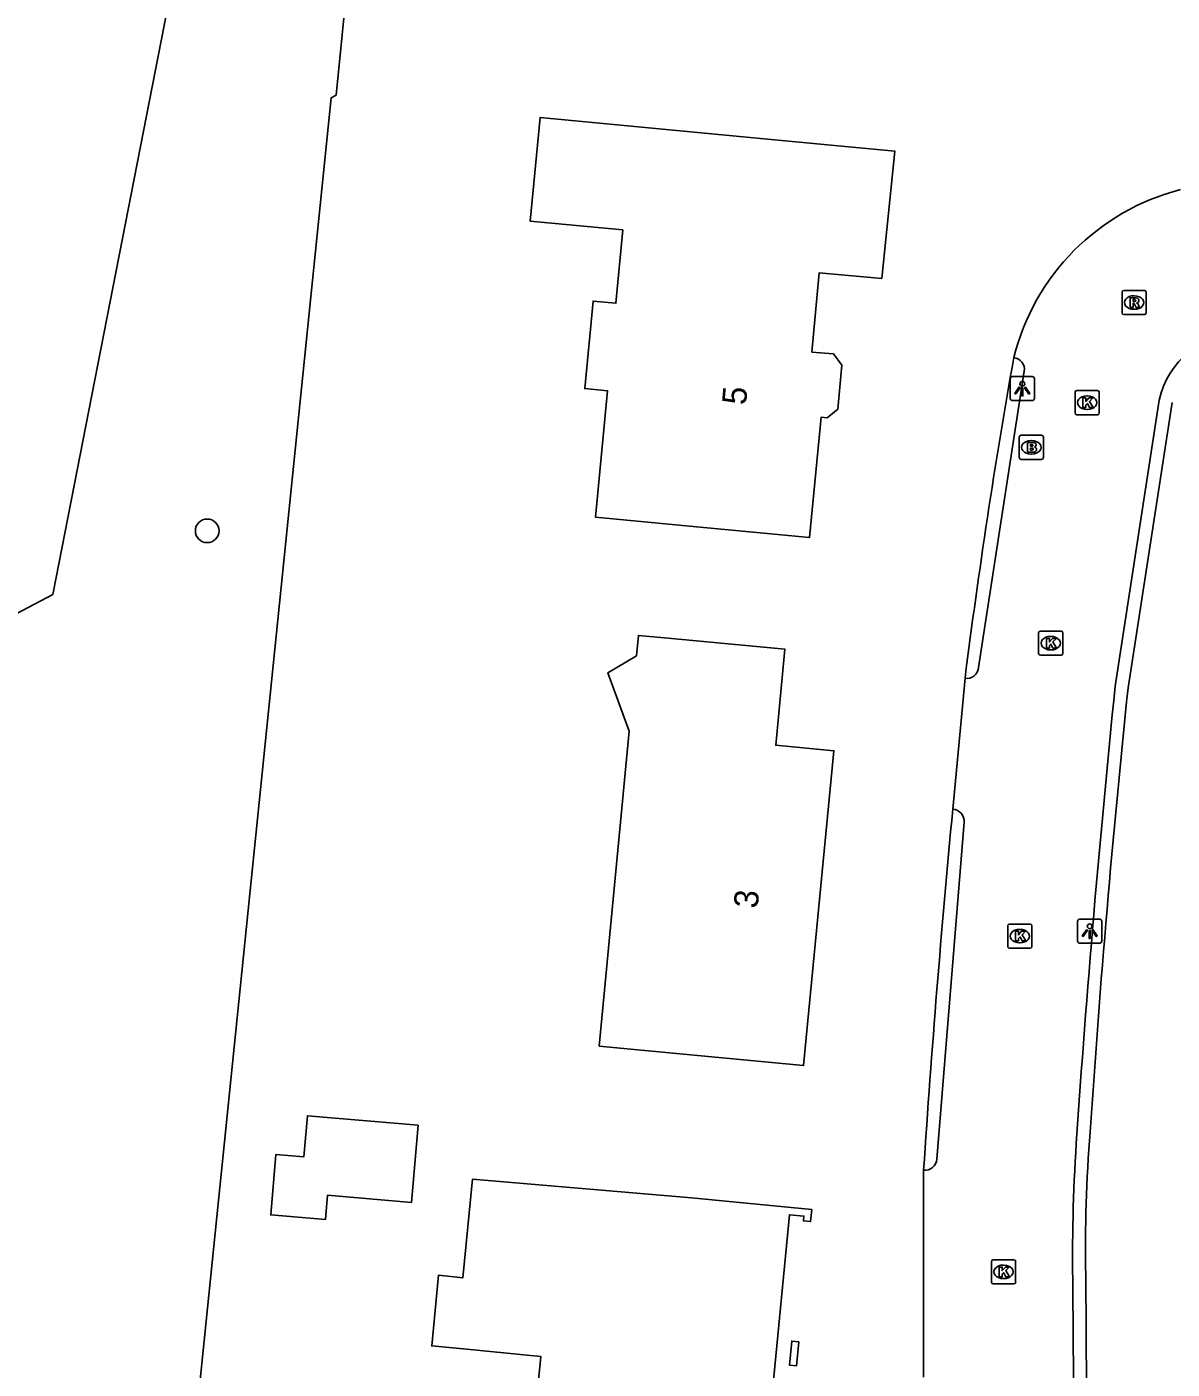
# Model space of a CAD drawing. Extents: x 162157 to 163165, y 378998 to 380775.
# Drawn here: x 162289.4 to 162336.8, y 380647 to 380702.5 of the extents above; entities that cross this region are included whole.
import ezdxf

# ---------------------------------------------------------------- set-up
doc = ezdxf.new("R2010")
doc.units = 0
for name, color, linetype in [('IMGEO_Boom', 7, 'Continuous'), ('IMGEO_Brandkraan', 7, 'Continuous'), ('IMGEO_Groenvoorziening', 7, 'Continuous'), ('IMGEO_Kolk', 7, 'Continuous'), ('IMGEO_Lichtpunt', 7, 'Continuous'), ('IMGEO_Pand', 7, 'Continuous'), ('IMGEO_Pand_nummerreeks', 7, 'Continuous'), ('IMGEO_Rijbaan_lokaal_open', 7, 'Continuous'), ('IMGEO_Rioolput', 7, 'Continuous'), ('IMGEO_Voetpad_open', 7, 'Continuous')]:
    doc.layers.add(name, color=color, linetype=linetype)

msp = doc.modelspace()

# ---------------------------------------------------------------- linework, layer by layer
at = {"layer": 'IMGEO_Boom'}
msp.add_circle((162296.826, 380681.67), 0.489, dxfattribs=at)
at = {"layer": 'IMGEO_Brandkraan'}
for p, q in [((162330.438, 380684.702), (162330.438, 380685.554)), ((162330.513, 380685.628), (162331.365, 380685.628)), ((162330.926, 380685.408), (162330.951, 380685.408)), ((162331.439, 380685.554), (162331.439, 380684.702)), ((162330.949, 380684.848), (162330.924, 380684.848)), ((162331.365, 380684.628), (162330.513, 380684.628))]:
    msp.add_line(p, q, dxfattribs=at)
for points in [[(162330.438, 380684.702), (162330.438, 380685.554)], [(162330.513, 380685.628), (162331.365, 380685.628)], [(162330.786, 380685.328), (162330.786, 380684.928), (162330.999, 380684.928)], [(162331.017, 380685.328), (162330.786, 380685.328)], [(162330.965, 380685.247), (162330.911, 380685.247), (162330.911, 380685.171)], [(162331.439, 380685.554), (162331.439, 380684.702)], [(162330.911, 380685.171), (162330.964, 380685.171)], [(162330.973, 380685.095), (162330.911, 380685.095), (162330.911, 380685.014)], [(162330.911, 380685.014), (162330.973, 380685.014)], [(162331.365, 380684.628), (162330.513, 380684.628)]]:
    msp.add_lwpolyline(points, dxfattribs=at)
for centre, radius, start, end in [((162330.515, 380685.552), 0.0765, 91.552, 178.448), ((162330.515, 380685.552), 0.0765, 91.552, 178.448), ((162330.966, 380685.209), 0.0379, 267.8285, 90.9355), ((162331.021, 380685.183), 0.145, 59.4692, 91.5367), ((162331.046, 380685.23), 0.0922, 285.5137, 58.1501), ((162331.363, 380685.552), 0.0765, 1.552, 88.448), ((162331.363, 380685.552), 0.0765, 1.552, 88.448), ((162330.515, 380684.704), 0.0765, 181.552, 268.448), ((162330.515, 380684.704), 0.0765, 181.552, 268.448), ((162330.974, 380685.054), 0.0404, 269.8759, 90.5077), ((162331.005, 380685.179), 0.251, 268.6676, 293.5347), ((162331.051, 380685.038), 0.105, 301.3115, 78.989), ((162331.363, 380684.704), 0.0765, 271.552, 358.448), ((162331.363, 380684.704), 0.0765, 271.552, 358.448)]:
    msp.add_arc(centre, radius, start, end, dxfattribs=at)
for centre, major_axis, ratio, start_param, end_param in [((162330.925, 380685.128), (-0.387, 0.002), 0.722429, 4.712389, 7.853982), ((162330.95, 380685.128), (-0.39, 0.002), 0.717154, 1.570796, 4.712389)]:
    msp.add_ellipse(centre, major_axis=major_axis, ratio=ratio, start_param=start_param, end_param=end_param, dxfattribs=at)
at = {"layer": 'IMGEO_Groenvoorziening'}
for points in [[(162295.473, 380636.096), (162301.962, 380699.607), (162302.171, 380699.713), (162304.371, 380721.939), (162315.245, 380730.525)], [(162288.388, 380677.953), (162290.44, 380679.036), (162295.923, 380707.125), (162296.214, 380708.615), (162296.259, 380708.847)]]:
    msp.add_lwpolyline(points, dxfattribs=at)
at = {"layer": 'IMGEO_Kolk'}
for p, q in [((162332.825, 380687.48), (162333.677, 380687.48)), ((162332.75, 380686.554), (162332.75, 380687.406)), ((162333.238, 380687.26), (162333.263, 380687.26)), ((162333.751, 380687.406), (162333.751, 380686.554)), ((162333.677, 380686.48), (162332.825, 380686.48)), ((162333.261, 380686.7), (162333.236, 380686.7)), ((162331.316, 380677.517), (162332.168, 380677.517)), ((162331.241, 380676.591), (162331.241, 380677.443)), ((162331.729, 380677.297), (162331.754, 380677.297)), ((162332.242, 380677.443), (162332.242, 380676.591)), ((162332.168, 380676.517), (162331.316, 380676.517)), ((162331.752, 380676.737), (162331.727, 380676.737)), ((162329.963, 380664.459), (162329.963, 380665.311)), ((162330.038, 380665.385), (162330.89, 380665.385)), ((162330.964, 380665.311), (162330.964, 380664.459)), ((162330.451, 380665.165), (162330.476, 380665.165)), ((162330.89, 380664.385), (162330.038, 380664.385)), ((162330.474, 380664.605), (162330.449, 380664.605)), ((162329.29, 380650.556), (162329.29, 380651.408)), ((162329.365, 380651.482), (162330.217, 380651.482)), ((162330.291, 380651.408), (162330.291, 380650.556)), ((162329.778, 380651.262), (162329.803, 380651.262)), ((162330.217, 380650.482), (162329.365, 380650.482)), ((162329.801, 380650.702), (162329.776, 380650.702))]:
    msp.add_line(p, q, dxfattribs=at)
for points in [[(162332.825, 380687.48), (162333.677, 380687.48)], [(162332.75, 380686.554), (162332.75, 380687.406)], [(162333.071, 380687.18), (162333.194, 380687.18), (162333.194, 380687.029), (162333.324, 380687.18), (162333.488, 380687.18), (162333.342, 380687.029), (162333.495, 380686.78), (162333.343, 380686.78), (162333.258, 380686.944), (162333.194, 380686.877), (162333.194, 380686.78), (162333.071, 380686.78), (162333.071, 380687.18)], [(162333.751, 380687.406), (162333.751, 380686.554)], [(162333.677, 380686.48), (162332.825, 380686.48)], [(162331.316, 380677.517), (162332.168, 380677.517)], [(162331.241, 380676.591), (162331.241, 380677.443)], [(162331.562, 380677.217), (162331.685, 380677.217), (162331.685, 380677.066), (162331.815, 380677.217), (162331.979, 380677.217), (162331.833, 380677.066), (162331.986, 380676.817), (162331.834, 380676.817), (162331.749, 380676.981), (162331.685, 380676.914), (162331.685, 380676.817), (162331.562, 380676.817), (162331.562, 380677.217)], [(162332.242, 380677.443), (162332.242, 380676.591)], [(162332.168, 380676.517), (162331.316, 380676.517)], [(162329.963, 380664.459), (162329.963, 380665.311)], [(162330.038, 380665.385), (162330.89, 380665.385)], [(162330.964, 380665.311), (162330.964, 380664.459)], [(162330.284, 380665.085), (162330.407, 380665.085), (162330.407, 380664.934), (162330.537, 380665.085), (162330.701, 380665.085), (162330.555, 380664.934), (162330.708, 380664.685), (162330.556, 380664.685), (162330.471, 380664.849), (162330.407, 380664.782), (162330.407, 380664.685), (162330.284, 380664.685), (162330.284, 380665.085)], [(162330.89, 380664.385), (162330.038, 380664.385)], [(162329.29, 380650.556), (162329.29, 380651.408)], [(162329.365, 380651.482), (162330.217, 380651.482)], [(162330.291, 380651.408), (162330.291, 380650.556)], [(162329.611, 380651.182), (162329.734, 380651.182), (162329.734, 380651.031), (162329.864, 380651.182), (162330.028, 380651.182), (162329.882, 380651.031), (162330.035, 380650.782), (162329.883, 380650.782), (162329.798, 380650.946), (162329.734, 380650.879), (162329.734, 380650.782), (162329.611, 380650.782), (162329.611, 380651.182)], [(162330.217, 380650.482), (162329.365, 380650.482)]]:
    msp.add_lwpolyline(points, dxfattribs=at)
for centre, start, end in [((162332.827, 380687.404), 91.552, 178.448), ((162332.827, 380687.404), 91.552, 178.448), ((162333.675, 380687.404), 1.552, 88.448), ((162333.675, 380687.404), 1.552, 88.448), ((162332.827, 380686.556), 181.552, 268.448), ((162332.827, 380686.556), 181.552, 268.448), ((162333.675, 380686.556), 271.552, 358.448), ((162333.675, 380686.556), 271.552, 358.448), ((162331.318, 380677.441), 91.552, 178.448), ((162331.318, 380677.441), 91.552, 178.448), ((162332.166, 380677.441), 1.552, 88.448), ((162332.166, 380677.441), 1.552, 88.448), ((162331.318, 380676.593), 181.552, 268.448), ((162331.318, 380676.593), 181.552, 268.448), ((162332.166, 380676.593), 271.552, 358.448), ((162332.166, 380676.593), 271.552, 358.448), ((162330.04, 380665.309), 91.552, 178.448), ((162330.04, 380665.309), 91.552, 178.448), ((162330.888, 380665.309), 1.552, 88.448), ((162330.888, 380665.309), 1.552, 88.448), ((162330.04, 380664.461), 181.552, 268.448), ((162330.04, 380664.461), 181.552, 268.448), ((162330.888, 380664.461), 271.552, 358.448), ((162330.888, 380664.461), 271.552, 358.448), ((162329.367, 380651.406), 91.552, 178.448), ((162329.367, 380651.406), 91.552, 178.448), ((162330.215, 380651.406), 1.552, 88.448), ((162330.215, 380651.406), 1.552, 88.448), ((162329.367, 380650.558), 181.552, 268.448), ((162329.367, 380650.558), 181.552, 268.448), ((162330.215, 380650.558), 271.552, 358.448), ((162330.215, 380650.558), 271.552, 358.448)]:
    msp.add_arc(centre, 0.0765, start, end, dxfattribs=at)
for centre, major_axis, ratio, start_param, end_param in [((162333.237, 380686.98), (-0.387, 0.002), 0.722429, 4.712389, 7.853982), ((162333.262, 380686.98), (-0.39, 0.002), 0.717154, 1.570796, 4.712389), ((162331.728, 380677.017), (-0.387, 0.002), 0.722429, 4.712389, 7.853982), ((162331.753, 380677.017), (-0.39, 0.002), 0.717154, 1.570796, 4.712389), ((162330.45, 380664.885), (-0.387, 0.002), 0.722429, 4.712389, 7.853982), ((162330.475, 380664.885), (-0.39, 0.002), 0.717154, 1.570796, 4.712389), ((162329.777, 380650.982), (-0.387, 0.002), 0.722429, 4.712389, 7.853982), ((162329.802, 380650.982), (-0.39, 0.002), 0.717154, 1.570796, 4.712389)]:
    msp.add_ellipse(centre, major_axis=major_axis, ratio=ratio, start_param=start_param, end_param=end_param, dxfattribs=at)
at = {"layer": 'IMGEO_Lichtpunt'}
for p, q in [((162330.97, 380688.057), (162330.162, 380688.057)), ((162330.97, 380688.057), (162330.162, 380688.057)), ((162330.068, 380687.962), (162330.068, 380687.155)), ((162330.068, 380687.962), (162330.068, 380687.155)), ((162331.064, 380687.155), (162331.064, 380687.962)), ((162331.064, 380687.155), (162331.064, 380687.962)), ((162330.162, 380687.061), (162330.97, 380687.061)), ((162330.162, 380687.061), (162330.97, 380687.061)), ((162332.857, 380665.494), (162332.857, 380664.687)), ((162332.857, 380665.494), (162332.857, 380664.687)), ((162333.759, 380665.589), (162332.951, 380665.589)), ((162333.759, 380665.589), (162332.951, 380665.589)), ((162333.853, 380664.687), (162333.853, 380665.494)), ((162333.853, 380664.687), (162333.853, 380665.494)), ((162332.951, 380664.593), (162333.759, 380664.593)), ((162332.951, 380664.593), (162333.759, 380664.593))]:
    msp.add_line(p, q, dxfattribs=at)
for points in [[(162330.442, 380687.626), (162330.481, 380687.598), (162330.293, 380687.336), (162330.255, 380687.363), (162330.442, 380687.626)], [(162330.544, 380687.578), (162330.591, 380687.578), (162330.591, 380687.256), (162330.544, 380687.256), (162330.544, 380687.578)], [(162330.654, 380687.598), (162330.692, 380687.625), (162330.879, 380687.363), (162330.84, 380687.335), (162330.654, 380687.598)], [(162333.231, 380665.158), (162333.27, 380665.13), (162333.082, 380664.868), (162333.044, 380664.895), (162333.231, 380665.158)], [(162333.333, 380665.11), (162333.38, 380665.11), (162333.38, 380664.788), (162333.333, 380664.788), (162333.333, 380665.11)], [(162333.443, 380665.13), (162333.481, 380665.157), (162333.668, 380664.895), (162333.629, 380664.867), (162333.443, 380665.13)]]:
    msp.add_lwpolyline(points, dxfattribs=at)
for centre in [(162330.567, 380687.76), (162333.356, 380665.292)]:
    msp.add_circle(centre, 0.0994, dxfattribs=at)
for centre, start, end in [((162330.162, 380687.962), 90, 180), ((162330.162, 380687.962), 90, 180), ((162330.97, 380687.962), 0, 90), ((162330.97, 380687.962), 0, 90), ((162330.162, 380687.155), 180, 270), ((162330.162, 380687.155), 180, 270), ((162330.97, 380687.155), 270, 0), ((162330.97, 380687.155), 270, 360), ((162332.951, 380665.494), 90, 180), ((162332.951, 380665.494), 90, 180), ((162333.759, 380665.494), 0, 90), ((162333.759, 380665.494), 0, 90), ((162332.951, 380664.687), 180, 270), ((162332.951, 380664.687), 180, 270), ((162333.759, 380664.687), 270, 0), ((162333.759, 380664.687), 270, 360)]:
    msp.add_arc(centre, 0.0946, start, end, dxfattribs=at)
at = {"layer": 'IMGEO_Pand'}
for points in [[(162320.315, 380697.862), (162310.604, 380698.787), (162310.195, 380694.496), (162314.029, 380694.132), (162313.741, 380691.095), (162312.796, 380691.186), (162312.452, 380687.562), (162313.398, 380687.472), (162312.9, 380682.235), (162316.786, 380681.865), (162321.763, 380681.391), (162322.238, 380686.371), (162322.487, 380686.348), (162322.926, 380686.702), (162323.1, 380688.529), (162322.745, 380688.994), (162321.859, 380689.074), (162322.158, 380692.357), (162324.745, 380692.12), (162325.292, 380697.388), (162320.315, 380697.862)], [(162316.538, 380660), (162321.515, 380659.526), (162322.768, 380672.561), (162320.363, 380672.789), (162320.739, 380676.765), (162315.762, 380677.238), (162314.675, 380677.341), (162314.594, 380676.488), (162313.406, 380675.788), (162314.298, 380673.373), (162313.056, 380660.331), (162316.538, 380660)], [(162305.556, 380657.055), (162300.973, 380657.449), (162300.827, 380655.745), (162299.672, 380655.844), (162299.457, 380653.34), (162301.721, 380653.146), (162301.808, 380654.155), (162305.281, 380653.857), (162305.556, 380657.055)], [(162320.068, 380644.491), (162320.926, 380653.349), (162321.523, 380653.291), (162321.504, 380653.092), (162321.803, 380653.063), (162321.851, 380653.561), (162316.875, 380654.044), (162307.809, 380654.824), (162307.413, 380650.734), (162306.396, 380650.843), (162306.122, 380647.916), (162307.848, 380647.749), (162309.937, 380647.547), (162310.634, 380647.479), (162310.118, 380642.154)], [(162321.32, 380648.087), (162321.022, 380648.116), (162320.925, 380647.12), (162321.224, 380647.091), (162321.32, 380648.087)]]:
    msp.add_lwpolyline(points, dxfattribs=at)
at = {"layer": 'IMGEO_Rijbaan_lokaal_open'}
for points in [[(162328.758, 380676.005), (162330.646, 380688.277)], [(162336.232, 380687.084), (162334.412, 380675.231)], [(162328.196, 380675.567), (162327.687, 380670.14)], [(162327.03, 380655.644), (162328.159, 380669.604)], [(162326.48, 380655.187), (162326.471, 380646.623)], [(162332.659, 380650.286), (162332.751, 380637.296)]]:
    msp.add_lwpolyline(points, dxfattribs=at)
for centre, radius, start, end in [((162339.49, 380686.545), 9.554, 104.4037, 166.0844), ((162339.66, 380686.326), 3.511, 90.0324, 167.5356), ((162330.157, 380688.352), 0.495, 351.2954, 83.1537), ((162328.282, 380676.037), 0.477, 259.6614, 356.2014), ((162880.043, 380619.242), 548.496, 174.14115, 176.12624), ((162327.659, 380669.64), 0.501, 355.9386, 86.7955), ((162403.824, 380651.624), 71.177, 176.23553, 181.07699), ((162326.534, 380655.681), 0.497, 263.7704, 355.6766)]:
    msp.add_arc(centre, radius, start, end, dxfattribs=at)
at = {"layer": 'IMGEO_Rioolput'}
for p, q in [((162334.693, 380690.698), (162334.693, 380691.55)), ((162334.768, 380691.624), (162335.62, 380691.624)), ((162335.181, 380691.404), (162335.206, 380691.404)), ((162335.694, 380691.55), (162335.694, 380690.698)), ((162335.204, 380690.844), (162335.179, 380690.844)), ((162335.62, 380690.624), (162334.768, 380690.624))]:
    msp.add_line(p, q, dxfattribs=at)
for points in [[(162334.693, 380690.698), (162334.693, 380691.55)], [(162334.768, 380691.624), (162335.62, 380691.624)], [(162335.694, 380691.55), (162335.694, 380690.698)], [(162335.282, 380691.322), (162335.03, 380691.324), (162335.03, 380690.924)], [(162335.03, 380690.924), (162335.154, 380690.924), (162335.154, 380691.086), (162335.165, 380691.086)], [(162335.208, 380691.243), (162335.154, 380691.243), (162335.154, 380691.162)], [(162335.154, 380691.162), (162335.206, 380691.162)], [(162335.212, 380691.057), (162335.283, 380690.924), (162335.423, 380690.924), (162335.358, 380691.05)], [(162335.62, 380690.624), (162334.768, 380690.624)]]:
    msp.add_lwpolyline(points, dxfattribs=at)
for centre, radius, start, end in [((162334.77, 380691.548), 0.0765, 91.552, 178.448), ((162334.77, 380691.548), 0.0765, 91.552, 178.448), ((162335.618, 380691.548), 0.0765, 1.552, 88.448), ((162335.618, 380691.548), 0.0765, 1.552, 88.448), ((162335.164, 380691.033), 0.0533, 26.0293, 88.6989), ((162335.19, 380691.351), 0.19, 274.7715, 282.9687), ((162335.214, 380691.147), 0.0964, 77.0061, 93.1865), ((162335.228, 380691.204), 0.0378, 276.6634, 79.6772), ((162335.281, 380691.212), 0.109, 350.3612, 89.416), ((162335.279, 380691.212), 0.112, 277.5842, 350.9817), ((162335.263, 380690.997), 0.108, 29.5134, 73.7905), ((162334.77, 380690.7), 0.0765, 181.552, 268.448), ((162334.77, 380690.7), 0.0765, 181.552, 268.448), ((162335.618, 380690.7), 0.0765, 271.552, 358.448), ((162335.618, 380690.7), 0.0765, 271.552, 358.448)]:
    msp.add_arc(centre, radius, start, end, dxfattribs=at)
for centre, major_axis, ratio, start_param, end_param in [((162335.18, 380691.124), (-0.387, 0.002), 0.722429, 4.712389, 7.853982), ((162335.205, 380691.124), (-0.39, 0.002), 0.717154, 1.570796, 4.712389)]:
    msp.add_ellipse(centre, major_axis=major_axis, ratio=ratio, start_param=start_param, end_param=end_param, dxfattribs=at)
at = {"layer": 'IMGEO_Voetpad_open'}
for points in [[(162336.768, 380686.979), (162334.945, 380675.165)], [(162333.191, 380650.844), (162333.284, 380636.819)]]:
    msp.add_lwpolyline(points, dxfattribs=at)
for centre, radius, start, end in [((162594.428, 380641.85), 268.359, 169.91485, 172.78226), ((162806.048, 380625.746), 473.688, 174.0115, 176.24301), ((162859.206, 380619.711), 533.906, 174.58014, 176.19009), ((162390.909, 380652), 57.729, 175.24639, 181.14729)]:
    msp.add_arc(centre, radius, start, end, dxfattribs=at)

# ---------------------------------------------------------------- texts
at = {"layer": 'IMGEO_Pand_nummerreeks'}
for s, rotation, p in [('5', 84.7961, (162319.126, 380686.858)), ('3', 84.5093, (162319.607, 380666.011))]:
    msp.add_text(s, height=1, rotation=rotation, dxfattribs=at).set_placement(p)

doc.saveas('drawing.dxf')
